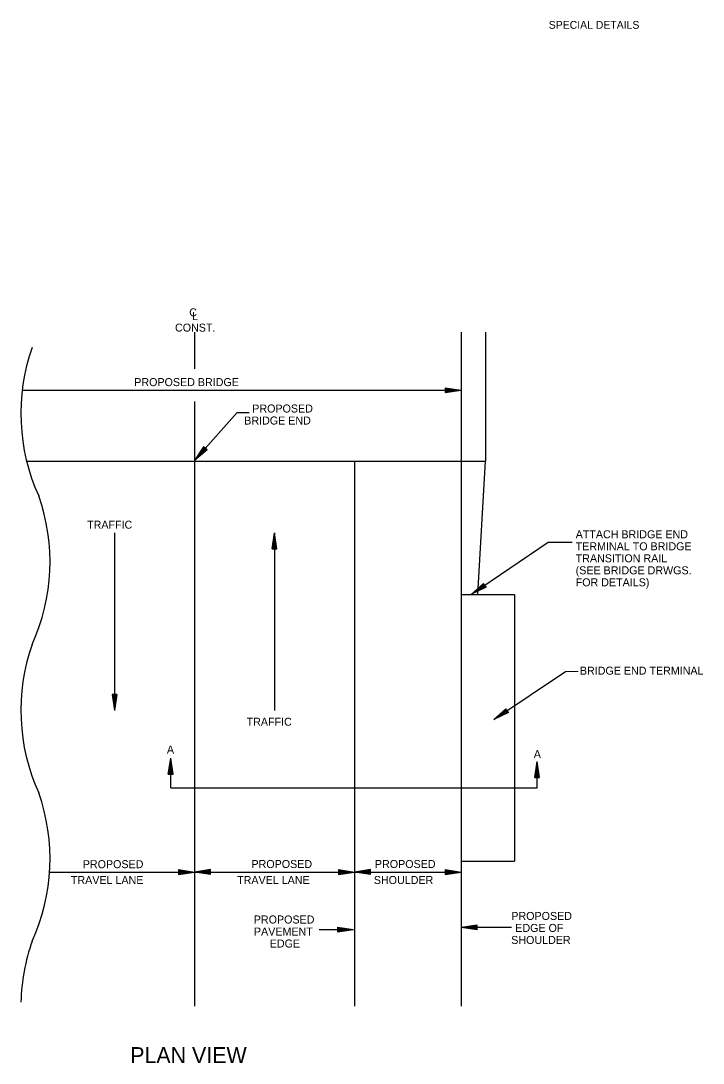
# Model space of a CAD drawing. Extents: x 1929624 to 1936506, y 596315 to 605721.
# Drawn here: x 1934824 to 1935336, y 603526 to 604308 of the extents above; entities that cross this region are included whole.
import ezdxf

# ---------------------------------------------------------------- set-up
doc = ezdxf.new("R2010")
doc.units = 0
doc.layers.add('Default', color=7, linetype='Continuous')
doc.layers.add('R_Border Prem', color=7, linetype='Continuous')

msp = doc.modelspace()

# ---------------------------------------------------------------- linework, layer by layer
at = {"layer": 'Default'}
for p, q in [((1934954.01, 604074.22), (1934954.01, 604046.61)), ((1935154.01, 604074.22), (1935154.01, 603977.42)), ((1935172.34, 604074.22), (1935172.34, 603977.42)), ((1934824.84, 604030.65), (1935154.01, 604030.65)), ((1935142.01, 604032.45), (1935154.01, 604030.65)), ((1935142.01, 604032.45), (1935142.01, 604028.85)), ((1935142.01, 604032.15), (1935152.01, 604030.65)), ((1935142.01, 604031.84), (1935149.94, 604030.65)), ((1935142.01, 604031.54), (1935147.94, 604030.65)), ((1935142.01, 604031.23), (1935145.91, 604030.65)), ((1935142.01, 604030.93), (1935143.91, 604030.65)), ((1935142.01, 604028.85), (1935154.01, 604030.65)), ((1935142.01, 604030.06), (1935145.91, 604030.65)), ((1935142.01, 604029.46), (1935149.94, 604030.65)), ((1935142.01, 604029.15), (1935152.01, 604030.65)), ((1935142.01, 604029.76), (1935147.94, 604030.65)), ((1935142.01, 604030.37), (1935143.91, 604030.65)), ((1934954.01, 604022.06), (1934954.01, 603568.67)), ((1934954.13, 603977.99), (1934986.01, 604013.77)), ((1934986.01, 604013.77), (1934995.05, 604013.79)), ((1934960.77, 603988.15), (1934954.13, 603977.99)), ((1934963.46, 603985.75), (1934954.13, 603977.99)), ((1934960.99, 603987.95), (1934955.46, 603979.49)), ((1934963.23, 603985.95), (1934955.46, 603979.49)), ((1934961.22, 603987.74), (1934956.84, 603981.03)), ((1934963, 603986.16), (1934956.84, 603981.03)), ((1934961.45, 603987.54), (1934958.17, 603982.52)), ((1934962.78, 603986.35), (1934958.17, 603982.52)), ((1934961.67, 603987.34), (1934959.52, 603984.04)), ((1934962.55, 603986.56), (1934959.52, 603984.04)), ((1934963.46, 603985.75), (1934960.77, 603988.15)), ((1934961.9, 603987.14), (1934960.85, 603985.53)), ((1934962.32, 603986.76), (1934960.85, 603985.53)), ((1934828.15, 603977.42), (1935172.34, 603977.42)), ((1935074.01, 603977.42), (1935074.01, 603568.67)), ((1935154.01, 603977.42), (1935154.01, 603877.42)), ((1935166.51, 603877.42), (1935172.34, 603977.42)), ((1934894.01, 603923.6), (1934894.01, 603790.49)), ((1935012.21, 603911.6), (1935014.01, 603923.6)), ((1935012.51, 603911.6), (1935014.01, 603921.6)), ((1935012.82, 603911.6), (1935014.01, 603919.53)), ((1935014.01, 603923.6), (1935014.01, 603790.49)), ((1935015.81, 603911.6), (1935014.01, 603923.6)), ((1935015.51, 603911.6), (1935014.01, 603921.6)), ((1935015.2, 603911.6), (1935014.01, 603919.53)), ((1935012.21, 603911.6), (1935015.81, 603911.6)), ((1935013.12, 603911.6), (1935014.01, 603917.53)), ((1935013.43, 603911.6), (1935014.01, 603915.5)), ((1935013.73, 603911.6), (1935014.01, 603913.5)), ((1935014.9, 603911.6), (1935014.01, 603917.53)), ((1935014.6, 603911.6), (1935014.01, 603915.5)), ((1935014.29, 603911.6), (1935014.01, 603913.5)), ((1935161.83, 603877.54), (1935219.34, 603916.53)), ((1935219.34, 603916.53), (1935237.43, 603916.53)), ((1935170.75, 603885.76), (1935161.83, 603877.54)), ((1935172.77, 603882.78), (1935161.83, 603877.54)), ((1935170.92, 603885.52), (1935163.49, 603878.66)), ((1935172.6, 603883.03), (1935163.49, 603878.66)), ((1935171.09, 603885.26), (1935165.2, 603879.82)), ((1935172.43, 603883.29), (1935165.2, 603879.82)), ((1935171.26, 603885.01), (1935166.85, 603880.94)), ((1935172.26, 603883.53), (1935166.85, 603880.94)), ((1935171.43, 603884.76), (1935168.53, 603882.09)), ((1935172.09, 603883.79), (1935168.53, 603882.09)), ((1935171.6, 603884.51), (1935170.19, 603883.21)), ((1935171.92, 603884.04), (1935170.19, 603883.21)), ((1935172.77, 603882.78), (1935170.75, 603885.76)), ((1935153.98, 603877.42), (1935153.98, 603677.42)), ((1935154.01, 603879.59), (1935154.01, 603568.67)), ((1935154.01, 603877.42), (1935194.05, 603877.42)), ((1935194.05, 603877.42), (1935194.05, 603677.42)), ((1935178.66, 603783.58), (1935232.27, 603819.77)), ((1935232.27, 603819.77), (1935241.73, 603819.84)), ((1934892.21, 603802.49), (1934894.01, 603790.49)), ((1934895.81, 603802.49), (1934892.21, 603802.49)), ((1934892.51, 603802.49), (1934894.01, 603792.49)), ((1934892.82, 603802.49), (1934894.01, 603794.56)), ((1934893.12, 603802.49), (1934894.01, 603796.56)), ((1934893.42, 603802.49), (1934894.01, 603798.59)), ((1934893.73, 603802.49), (1934894.01, 603800.59)), ((1934895.81, 603802.49), (1934894.01, 603790.49)), ((1934894.59, 603802.49), (1934894.01, 603798.59)), ((1934895.2, 603802.49), (1934894.01, 603794.56)), ((1934895.51, 603802.49), (1934894.01, 603792.49)), ((1934894.9, 603802.49), (1934894.01, 603796.56)), ((1934894.29, 603802.49), (1934894.01, 603800.59)), ((1935187.6, 603791.79), (1935178.66, 603783.58)), ((1935189.61, 603788.8), (1935178.66, 603783.58)), ((1935187.77, 603791.54), (1935180.32, 603784.7)), ((1935189.45, 603789.05), (1935180.32, 603784.7)), ((1935187.94, 603791.28), (1935182.03, 603785.86)), ((1935189.27, 603789.3), (1935182.03, 603785.86)), ((1935188.11, 603791.04), (1935183.69, 603786.97)), ((1935189.11, 603789.55), (1935183.69, 603786.97)), ((1935188.28, 603790.78), (1935185.37, 603788.11)), ((1935188.93, 603789.81), (1935185.37, 603788.11)), ((1935188.45, 603790.53), (1935187.03, 603789.23)), ((1935188.76, 603790.06), (1935187.03, 603789.23)), ((1935189.61, 603788.8), (1935187.6, 603791.79)), ((1934934.42, 603742.8), (1934936.22, 603754.8)), ((1934934.72, 603742.8), (1934936.22, 603752.8)), ((1934935.03, 603742.8), (1934936.22, 603750.73)), ((1934935.33, 603742.8), (1934936.22, 603748.73)), ((1934936.22, 603732.54), (1934936.22, 603754.8)), ((1934938.02, 603742.8), (1934936.22, 603754.8)), ((1934937.72, 603742.8), (1934936.22, 603752.8)), ((1934937.41, 603742.8), (1934936.22, 603750.73)), ((1934937.11, 603742.8), (1934936.22, 603748.73)), ((1935209.27, 603740.26), (1935211.07, 603752.26)), ((1935209.57, 603740.26), (1935211.07, 603750.26)), ((1935209.88, 603740.26), (1935211.07, 603748.19)), ((1935211.07, 603732.54), (1935211.07, 603752.26)), ((1935212.87, 603740.26), (1935211.07, 603752.26)), ((1935212.57, 603740.26), (1935211.07, 603750.26)), ((1935212.26, 603740.26), (1935211.07, 603748.19)), ((1934934.42, 603742.8), (1934938.02, 603742.8)), ((1934935.64, 603742.8), (1934936.22, 603746.7)), ((1934935.94, 603742.8), (1934936.22, 603744.7)), ((1934936.81, 603742.8), (1934936.22, 603746.7)), ((1934936.5, 603742.8), (1934936.22, 603744.7)), ((1935209.27, 603740.26), (1935212.87, 603740.26)), ((1935210.18, 603740.26), (1935211.07, 603746.19)), ((1935210.49, 603740.26), (1935211.07, 603744.16)), ((1935210.79, 603740.26), (1935211.07, 603742.16)), ((1935211.96, 603740.26), (1935211.07, 603746.19)), ((1935211.66, 603740.26), (1935211.07, 603744.16)), ((1935211.35, 603740.26), (1935211.07, 603742.16)), ((1934936.22, 603732.54), (1935211.07, 603732.54)), ((1935154.01, 603677.42), (1935194.05, 603677.42)), ((1934845.38, 603669.31), (1934954.01, 603669.31)), ((1934942.01, 603671.11), (1934954.01, 603669.31)), ((1934942.01, 603671.11), (1934942.01, 603667.51)), ((1934942.01, 603670.81), (1934952.01, 603669.31)), ((1934942.01, 603670.5), (1934949.94, 603669.31)), ((1934942.01, 603670.2), (1934947.94, 603669.31)), ((1934942.01, 603669.89), (1934945.91, 603669.31)), ((1934942.01, 603669.59), (1934943.91, 603669.31)), ((1934942.01, 603667.51), (1934954.01, 603669.31)), ((1934942.01, 603668.72), (1934945.91, 603669.31)), ((1934942.01, 603668.12), (1934949.94, 603669.31)), ((1934942.01, 603667.81), (1934952.01, 603669.31)), ((1934942.01, 603668.42), (1934947.94, 603669.31)), ((1934942.01, 603669.03), (1934943.91, 603669.31)), ((1934966.01, 603671.11), (1934954.01, 603669.31)), ((1934966.01, 603667.51), (1934954.01, 603669.31)), ((1934954.01, 603669.31), (1935074.01, 603669.31)), ((1934966.01, 603670.81), (1934956.01, 603669.31)), ((1934966.01, 603667.81), (1934956.01, 603669.31)), ((1934966.01, 603670.5), (1934958.08, 603669.31)), ((1934966.01, 603668.12), (1934958.08, 603669.31)), ((1934966.01, 603670.2), (1934960.08, 603669.31)), ((1934966.01, 603668.42), (1934960.08, 603669.31)), ((1934966.01, 603669.9), (1934962.11, 603669.31)), ((1934966.01, 603668.73), (1934962.11, 603669.31)), ((1934966.01, 603669.59), (1934964.11, 603669.31)), ((1934966.01, 603669.03), (1934964.11, 603669.31)), ((1934966.01, 603667.51), (1934966.01, 603671.11)), ((1935062.01, 603671.11), (1935074.01, 603669.31)), ((1935062.01, 603671.11), (1935062.01, 603667.51)), ((1935062.01, 603670.81), (1935072.01, 603669.31)), ((1935062.01, 603670.5), (1935069.94, 603669.31)), ((1935062.01, 603670.2), (1935067.94, 603669.31)), ((1935062.01, 603669.89), (1935065.91, 603669.31)), ((1935062.01, 603669.59), (1935063.91, 603669.31)), ((1935062.01, 603667.51), (1935074.01, 603669.31)), ((1935062.01, 603668.72), (1935065.91, 603669.31)), ((1935062.01, 603668.12), (1935069.94, 603669.31)), ((1935062.01, 603667.81), (1935072.01, 603669.31)), ((1935062.01, 603668.42), (1935067.94, 603669.31)), ((1935062.01, 603669.03), (1935063.91, 603669.31)), ((1935086.01, 603671.11), (1935074.01, 603669.31)), ((1935074.01, 603669.31), (1935154.01, 603669.31)), ((1935086.01, 603667.51), (1935074.01, 603669.31)), ((1935086.01, 603670.81), (1935076.01, 603669.31)), ((1935086.01, 603667.81), (1935076.01, 603669.31)), ((1935086.01, 603670.5), (1935078.08, 603669.31)), ((1935086.01, 603668.12), (1935078.08, 603669.31)), ((1935086.01, 603670.2), (1935080.08, 603669.31)), ((1935086.01, 603668.42), (1935080.08, 603669.31)), ((1935086.01, 603669.9), (1935082.11, 603669.31)), ((1935086.01, 603668.73), (1935082.11, 603669.31)), ((1935086.01, 603669.59), (1935084.11, 603669.31)), ((1935086.01, 603669.03), (1935084.11, 603669.31)), ((1935086.01, 603667.51), (1935086.01, 603671.11)), ((1935142.01, 603671.11), (1935154.01, 603669.31)), ((1935142.01, 603671.11), (1935142.01, 603667.51)), ((1935142.01, 603670.81), (1935152.01, 603669.31)), ((1935142.01, 603670.5), (1935149.94, 603669.31)), ((1935142.01, 603670.2), (1935147.94, 603669.31)), ((1935142.01, 603669.89), (1935145.91, 603669.31)), ((1935142.01, 603669.59), (1935143.91, 603669.31)), ((1935142.01, 603667.51), (1935154.01, 603669.31)), ((1935142.01, 603668.72), (1935145.91, 603669.31)), ((1935142.01, 603668.12), (1935149.94, 603669.31)), ((1935142.01, 603667.81), (1935152.01, 603669.31)), ((1935142.01, 603668.42), (1935147.94, 603669.31)), ((1935142.01, 603669.03), (1935143.91, 603669.31)), ((1935047.45, 603626.19), (1935073.3, 603626.19)), ((1935061.3, 603627.99), (1935073.3, 603626.19)), ((1935061.3, 603627.99), (1935061.3, 603624.39)), ((1935061.3, 603627.69), (1935071.3, 603626.19)), ((1935061.3, 603627.38), (1935069.23, 603626.19)), ((1935061.3, 603627.08), (1935067.23, 603626.19)), ((1935061.3, 603626.77), (1935065.2, 603626.19)), ((1935061.3, 603626.47), (1935063.2, 603626.19)), ((1935061.3, 603624.39), (1935073.3, 603626.19)), ((1935061.3, 603625.6), (1935065.2, 603626.19)), ((1935061.3, 603625), (1935069.23, 603626.19)), ((1935061.3, 603624.69), (1935071.3, 603626.19)), ((1935061.3, 603625.3), (1935067.23, 603626.19)), ((1935061.3, 603625.91), (1935063.2, 603626.19)), ((1935166.01, 603629.58), (1935154.01, 603627.78)), ((1935191.87, 603627.78), (1935154.01, 603627.78)), ((1935166.01, 603625.98), (1935154.01, 603627.78)), ((1935166.01, 603629.28), (1935156.01, 603627.78)), ((1935166.01, 603626.28), (1935156.01, 603627.78)), ((1935166.01, 603628.97), (1935158.08, 603627.78)), ((1935166.01, 603626.59), (1935158.08, 603627.78)), ((1935166.01, 603628.67), (1935160.08, 603627.78)), ((1935166.01, 603626.89), (1935160.08, 603627.78)), ((1935166.01, 603628.37), (1935162.11, 603627.78)), ((1935166.01, 603627.2), (1935162.11, 603627.78)), ((1935166.01, 603628.06), (1935164.11, 603627.78)), ((1935166.01, 603627.5), (1935164.11, 603627.78)), ((1935166.01, 603625.98), (1935166.01, 603629.58))]:
    msp.add_line(p, q, dxfattribs=at)
for centre, start, end in [((1934972.64, 604013.11), 160.57465, 204.52912), ((1934696.87, 603901.82), 335.47088, 19.42535), ((1934972.64, 603790.53), 160.57465, 204.52912), ((1934696.87, 603679.24), 335.47088, 19.42535), ((1934972.64, 603567.95), 160.57465, 178.55672)]:
    msp.add_arc(centre, 148.84, start, end, dxfattribs=at)

# ---------------------------------------------------------------- texts
for s, height, p in [('C', 6, (1934950.09, 604085.95)), ('L', 6, (1934952.2, 604083.14)), ('CONST.', 6, (1934939.46, 604074.51)), ('PROPOSED BRIDGE', 6, (1934908.88, 604033.65)), ('PROPOSED', 6, (1934997.37, 604013.85)), ('BRIDGE END', 6, (1934991.37, 604004.85)), ('TRAFFIC', 6, (1934873.51, 603926.74)), ('ATTACH BRIDGE END', 6, (1935239.96, 603919.54)), ('TERMINAL TO BRIDGE', 6, (1935239.96, 603910.54)), ('TRANSITION RAIL', 6, (1935239.96, 603901.54)), ('(SEE BRIDGE DRWGS.', 6, (1935239.96, 603892.54)), ('FOR DETAILS)', 6, (1935239.96, 603883.54)), ('BRIDGE END TERMINAL', 6, (1935243.12, 603817.28)), ('TRAFFIC', 6, (1934993.15, 603778.98)), ('A', 6, (1934933.36, 603758.17)), ('A', 6, (1935208.54, 603754.78)), ('PROPOSED', 6, (1934870.27, 603672.19)), ('PROPOSED', 6, (1934996.79, 603672.31)), ('PROPOSED', 6, (1935089.39, 603672.31)), ('TRAVEL LANE', 6, (1934861.35, 603660.31)), ('TRAVEL LANE', 6, (1934986.04, 603660.31)), ('SHOULDER', 6, (1935088.57, 603660.31)), ('PROPOSED', 6, (1935191.69, 603633.38)), ('PROPOSED', 6, (1934998.54, 603630.71)), ('EDGE OF', 6, (1935194.66, 603624.38)), ('PAVEMENT', 6, (1934998.65, 603621.71)), ('EDGE', 6, (1935010.5, 603612.71)), ('SHOULDER', 6, (1935191.61, 603615.38)), ('PLAN VIEW', 12, (1934905.82, 603526))]:
    msp.add_text(s, height=height, rotation=360, dxfattribs=at).set_placement(p)
at = {"layer": 'R_Border Prem'}
msp.add_text('SPECIAL DETAILS', height=5.862, rotation=360, dxfattribs=at).set_placement((1935219.77, 604301.58))

doc.saveas('drawing.dxf')
